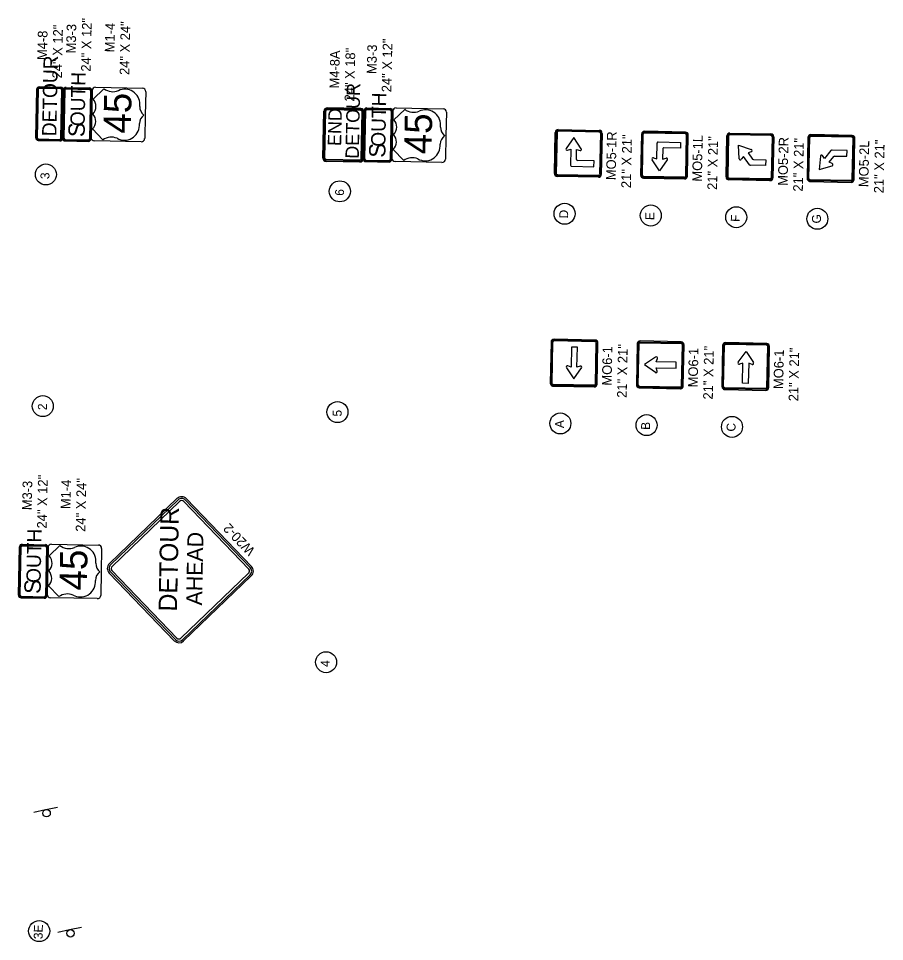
# Model space of a CAD drawing. Extents: x 327762 to 372792, y 127949 to 259367.
# Drawn here: x 351032 to 363148, y 246453 to 259367 of the extents above; entities that cross this region are included whole.
import ezdxf

# ---------------------------------------------------------------- set-up
doc = ezdxf.new("R2010")
doc.units = 0
for name, color, linetype in [('CA-TEXT', 7, 'Continuous'), ('P_SGN_Cell', 7, 'Continuous'), ('SIGNS-POLES', 7, 'Continuous')]:
    doc.layers.add(name, color=color, linetype=linetype)

msp = doc.modelspace()

# ---------------------------------------------------------------- linework, layer by layer
at = {"layer": 'CA-TEXT'}
for centre in [(351416, 257184), (355528, 256948), (358672, 256635), (359878, 256610), (361073, 256586), (362208, 256564), (351373, 253943), (355495, 253860), (358613, 253701), (359819, 253677), (361014, 253653), (355336, 250361), (351322, 246599)]:
    msp.add_circle(centre, 147, dxfattribs=at)
at = {"layer": 'P_SGN_Cell'}
for p, q in [((352110, 258404), (352766, 258390)), ((351648, 257690), (351662, 258366)), ((351658, 257691), (351671, 258366)), ((351670, 257690), (351684, 258365)), ((351700, 258402), (352025, 258396)), ((351700, 258393), (352025, 258387)), ((351700, 258381), (352025, 258374)), ((352040, 258358), (352026, 257683)), ((352052, 258358), (352039, 257683)), ((352062, 258358), (352048, 257683)), ((352048, 257702), (352062, 258358)), ((352229, 258383), (352077, 258238)), ((352812, 258343), (352805, 258014)), ((352812, 258343), (352812, 258343)), ((352730, 258135), (352730, 258165)), ((355292, 257414), (355306, 258070)), ((355304, 257413), (355317, 258069)), ((355320, 257413), (355333, 258069)), ((355822, 258106), (355353, 258116)), ((355822, 258094), (355353, 258104)), ((355821, 258079), (355353, 258088)), ((355827, 257403), (355841, 258059)), ((355843, 257402), (355856, 258059)), ((355855, 257402), (355868, 258078)), ((355855, 257402), (355868, 258058)), ((355864, 257403), (355878, 258077)), ((355877, 257402), (355890, 258077)), ((355906, 258105), (356231, 258098)), ((355906, 258092), (356231, 258086)), ((355907, 258114), (356232, 258108)), ((356246, 258070), (356233, 257395)), ((356259, 258070), (356245, 257395)), ((356255, 257413), (356268, 258069)), ((356268, 258069), (356255, 257395)), ((356435, 258095), (356283, 257949)), ((356316, 258115), (356972, 258102)), ((357018, 258054), (357011, 257726)), ((357018, 258054), (357018, 258054)), ((352724, 257867), (352725, 257897)), ((352805, 258014), (352798, 257686)), ((352068, 257821), (352214, 257669)), ((356936, 257847), (356937, 257877)), ((358530, 257199), (358542, 257773)), ((358553, 257772), (358541, 257198)), ((358567, 257772), (358555, 257198)), ((359157, 257777), (358583, 257788)), ((358584, 257813), (359158, 257801)), ((359158, 257790), (358584, 257802)), ((359173, 257760), (359162, 257186)), ((359187, 257760), (359176, 257186)), ((359198, 257759), (359186, 257185)), ((360363, 257777), (359789, 257789)), ((360363, 257766), (359789, 257778)), ((360363, 257752), (359789, 257764)), ((360984, 257764), (361558, 257753)), ((351685, 257674), (352010, 257668)), ((351685, 257662), (352010, 257655)), ((351685, 257653), (352010, 257646)), ((352751, 257641), (352094, 257654)), ((357011, 257726), (357005, 257398)), ((358803, 257702), (358693, 257549)), ((358906, 257545), (358803, 257702)), ((359747, 257748), (359736, 257174)), ((359747, 257174), (359758, 257748)), ((359760, 257174), (359772, 257748)), ((359983, 257640), (360295, 257633)), ((360295, 257633), (360293, 257551)), ((360367, 257162), (360379, 257736)), ((360381, 257161), (360392, 257735)), ((360392, 257161), (360403, 257735)), ((360931, 257150), (360942, 257724)), ((360953, 257724), (360942, 257150)), ((360967, 257724), (360955, 257150)), ((361558, 257742), (360984, 257754)), ((361558, 257728), (360984, 257740)), ((361574, 257712), (361562, 257138)), ((361588, 257711), (361576, 257137)), ((361599, 257711), (361587, 257137)), ((362077, 257701), (362066, 257127)), ((362077, 257127), (362088, 257701)), ((362090, 257127), (362102, 257701)), ((362693, 257730), (362119, 257742)), ((362693, 257719), (362119, 257731)), ((362693, 257705), (362119, 257717)), ((362697, 257115), (362709, 257689)), ((362711, 257114), (362723, 257688)), ((362722, 257114), (362733, 257688)), ((356275, 257533), (356421, 257381)), ((356931, 257579), (356931, 257609)), ((358711, 257524), (358759, 257537)), ((358759, 257537), (358754, 257314)), ((358838, 257392), (358841, 257535)), ((358841, 257535), (358888, 257520)), ((359962, 257401), (359966, 257624)), ((360047, 257543), (360044, 257399)), ((360293, 257551), (360061, 257556)), ((361114, 257405), (361106, 257592)), ((361106, 257592), (361284, 257532)), ((361284, 257502), (361238, 257485)), ((362398, 257518), (362307, 257407)), ((362623, 257521), (362413, 257525)), ((362622, 257439), (362623, 257521)), ((355807, 257384), (355339, 257393)), ((355807, 257368), (355339, 257377)), ((355892, 257386), (356217, 257380)), ((355892, 257374), (356217, 257367)), ((359084, 257373), (358851, 257378)), ((359082, 257291), (359084, 257373)), ((359999, 257235), (359896, 257391)), ((359915, 257416), (359962, 257401)), ((360109, 257387), (359999, 257235)), ((360044, 257399), (360091, 257413)), ((361173, 257435), (361143, 257396)), ((361259, 257321), (361173, 257435)), ((361238, 257485), (361302, 257400)), ((361313, 257394), (361485, 257391)), ((361485, 257391), (361484, 257309)), ((362250, 257440), (362235, 257253)), ((362307, 257407), (362280, 257448)), ((362371, 257355), (362438, 257437)), ((362449, 257442), (362622, 257439)), ((355807, 257356), (355338, 257366)), ((355891, 257364), (356216, 257358)), ((356957, 257352), (356301, 257366)), ((358770, 257298), (359082, 257291)), ((361484, 257309), (361274, 257313)), ((362235, 257253), (362415, 257305)), ((362417, 257336), (362371, 257355)), ((359145, 257170), (358571, 257181)), ((359145, 257156), (358571, 257168)), ((359145, 257145), (358571, 257157)), ((360350, 257146), (359776, 257157)), ((360350, 257132), (359776, 257143)), ((359776, 257132), (360350, 257121)), ((361545, 257108), (360971, 257119)), ((361546, 257121), (360972, 257133)), ((361545, 257097), (360971, 257108)), ((362681, 257099), (362106, 257110)), ((362680, 257085), (362106, 257096)), ((362106, 257086), (362680, 257074)), ((358483, 254839), (358471, 254265)), ((358482, 254265), (358494, 254839)), ((358496, 254265), (358507, 254839)), ((359099, 254857), (358524, 254868)), ((359098, 254843), (358524, 254855)), ((359099, 254868), (358525, 254879)), ((359103, 254252), (359114, 254826)), ((359116, 254252), (359128, 254826)), ((359127, 254252), (359139, 254826)), ((359688, 254815), (359677, 254241)), ((359687, 254241), (359699, 254815)), ((359701, 254240), (359713, 254814)), ((359729, 254830), (360304, 254819)), ((360304, 254843), (359730, 254855)), ((359730, 254844), (360304, 254833)), ((360308, 254228), (360320, 254802)), ((360322, 254228), (360333, 254802)), ((360333, 254228), (360344, 254802)), ((360883, 254791), (360872, 254217)), ((360883, 254216), (360894, 254791)), ((360896, 254216), (360908, 254790)), ((361499, 254819), (360925, 254831)), ((361499, 254808), (360925, 254820)), ((361499, 254795), (360925, 254806)), ((358769, 254770), (358763, 254490)), ((358851, 254769), (358769, 254770)), ((358845, 254489), (358851, 254769)), ((361100, 254556), (361210, 254708)), ((361210, 254708), (361313, 254552)), ((361503, 254204), (361515, 254778)), ((361517, 254204), (361528, 254778)), ((361528, 254203), (361539, 254778)), ((359946, 254629), (359789, 254526)), ((359955, 254563), (359970, 254610)), ((360235, 254558), (359955, 254563)), ((360234, 254476), (360235, 254558)), ((361166, 254544), (361118, 254530)), ((361160, 254264), (361166, 254544)), ((361248, 254542), (361242, 254262)), ((361294, 254527), (361248, 254542)), ((358697, 254481), (358801, 254324)), ((358763, 254490), (358716, 254506)), ((358801, 254324), (358910, 254477)), ((358892, 254502), (358845, 254489)), ((359789, 254526), (359942, 254416)), ((359967, 254434), (359954, 254481)), ((359954, 254481), (360234, 254476)), ((358511, 254223), (359086, 254212)), ((359086, 254236), (358512, 254248)), ((359086, 254223), (358512, 254234)), ((359717, 254224), (360291, 254212)), ((359717, 254210), (360291, 254198)), ((359717, 254199), (360291, 254187)), ((361487, 254188), (360912, 254199)), ((361486, 254174), (360912, 254186)), ((360912, 254175), (361486, 254163)), ((361242, 254262), (361160, 254264)), ((351032, 251299), (351046, 251975)), ((351042, 251300), (351055, 251975)), ((351054, 251300), (351068, 251974)), ((351084, 252012), (351409, 252005)), ((351084, 252002), (351409, 251996)), ((351084, 251990), (351409, 251983)), ((351424, 251967), (351411, 251292)), ((351437, 251967), (351423, 251292)), ((351446, 251967), (351432, 251292)), ((351433, 251311), (351446, 251967)), ((351613, 251992), (351461, 251847)), ((351494, 252013), (352150, 251999)), ((352196, 251952), (352189, 251624)), ((352196, 251952), (352196, 251952)), ((352114, 251744), (352115, 251774)), ((352189, 251624), (352183, 251296)), ((351453, 251430), (351598, 251278)), ((352109, 251476), (352109, 251506)), ((351069, 251271), (351394, 251265)), ((351069, 251262), (351394, 251255)), ((351070, 251284), (351395, 251277)), ((352135, 251250), (351479, 251263))]:
    msp.add_line(p, q, dxfattribs=at)
for points in [[(351625, 258403), (351325, 258409)], [(351287, 258373), (351273, 257698)], [(351296, 258373), (351283, 257698)], [(351309, 258372), (351295, 257697)], [(351625, 258394), (351325, 258400)], [(351625, 258382), (351325, 258388)], [(351626, 257691), (351640, 258366)], [(351639, 257691), (351652, 258365)], [(351648, 257690), (351662, 258365)], [(351310, 257682), (351610, 257675)], [(351310, 257669), (351610, 257663)], [(351310, 257660), (351610, 257654)], [(353250, 252649), (352304, 251740)], [(353267, 252632), (352320, 251723)], [(353287, 252610), (352341, 251701)], [(354253, 251664), (353344, 252610)], [(354274, 251684), (353365, 252630)], [(354291, 251701), (353383, 252647)], [(352301, 251607), (353210, 250661)], [(352318, 251624), (353228, 250677)], [(352340, 251644), (353249, 250698)], [(353306, 250697), (354252, 251606)], [(353326, 250675), (354273, 251585)], [(353343, 250658), (354289, 251567)]]:
    msp.add_lwpolyline(points, dxfattribs=at)
for centre, radius, start, end in [((351324, 258372), 37.5, 88.8468, 178.8468), ((351624, 258366), 37.5, 358.8468, 88.8468), ((352109, 258357), 46.9, 88.8462, 178.8462), ((351324, 258372), 28.1, 88.8468, 178.8468), ((351324, 258372), 15.6, 88.8468, 178.8468), ((351624, 258366), 28.1, 358.8468, 88.8468), ((351624, 258366), 15.6, 358.8468, 88.8468), ((351699, 258365), 37.5, 88.8462, 178.8462), ((351699, 258365), 28.1, 88.8462, 178.8462), ((351699, 258365), 15.6, 88.8462, 178.8462), ((352024, 258358), 37.5, 358.8462, 88.8462), ((352024, 258358), 28.1, 358.8462, 88.8462), ((352024, 258358), 15.6, 358.8462, 88.8462), ((352354, 258550), 208, 233.1143, 291.9873), ((352522, 258169), 208, 358.8462, 115.6928), ((352765, 258343), 46.9, 358.8462, 88.8462), ((351968, 258136), 149, 314.4191, 43.2734), ((351964, 257927), 149, 314.4191, 43.2734), ((352880, 258133), 151, 179.1885, 231.634), ((355352, 258069), 46.9, 88.8468, 178.8468), ((355352, 258069), 35.2, 88.8468, 178.8468), ((355352, 258069), 19.5, 88.8468, 178.8468), ((355821, 258059), 19.5, 358.8468, 88.8468), ((355821, 258059), 46.9, 358.8468, 88.8468), ((355821, 258059), 35.2, 358.8468, 88.8468), ((355906, 258077), 37.5, 88.8462, 178.8462), ((355906, 258077), 28.1, 88.8462, 178.8462), ((355906, 258077), 15.6, 88.8462, 178.8462), ((356231, 258070), 28.1, 358.8462, 88.8462), ((356231, 258070), 15.6, 358.8462, 88.8462), ((356231, 258070), 37.5, 358.8462, 88.8462), ((356315, 258069), 46.9, 88.8462, 178.8462), ((356560, 258262), 208, 233.1143, 291.9873), ((356728, 257881), 208, 358.8462, 115.6928), ((356971, 258055), 46.9, 358.8462, 88.8462), ((352875, 257893), 151, 126.0584, 178.5039), ((356175, 257847), 149, 314.4191, 43.2734), ((352516, 257871), 208, 240.0981, 358.8463), ((357087, 257845), 151, 179.1885, 231.634), ((358583, 257772), 41, 88.8462, 178.8462), ((358583, 257772), 30.1, 88.8462, 178.8462), ((358583, 257772), 16.4, 88.8462, 178.8462), ((359157, 257760), 16.4, 358.8462, 88.8462), ((359157, 257760), 41, 358.8462, 88.8462), ((359157, 257760), 30.1, 358.8462, 88.8462), ((359788, 257748), 41, 88.8462, 178.8462), ((359788, 257748), 30.1, 88.8462, 178.8462), ((359788, 257748), 16.4, 88.8462, 178.8462), ((360362, 257736), 41, 358.8462, 88.8462), ((360362, 257736), 30.1, 358.8462, 88.8462), ((360983, 257723), 41, 88.8462, 178.8462), ((360983, 257723), 41, 88.8462, 113.5578), ((351311, 257697), 37.5, 178.8468, 268.8468), ((351311, 257697), 28.1, 178.8468, 268.8468), ((351311, 257697), 15.6, 178.8468, 268.8468), ((351311, 257697), 15.6, 178.8468, 186.1883), ((351611, 257691), 28.1, 268.8468, 358.8468), ((351611, 257691), 15.6, 268.8468, 358.8468), ((351611, 257691), 37.5, 268.8468, 358.8468), ((351686, 257690), 37.5, 179.6119, 268.8462), ((351686, 257690), 28.1, 178.8462, 268.8462), ((351686, 257690), 15.6, 178.8462, 268.8462), ((352011, 257684), 28.1, 268.8462, 358.8462), ((352011, 257684), 15.6, 268.8462, 358.8462), ((352011, 257684), 37.5, 268.8462, 358.8462), ((352095, 257701), 46.9, 178.8462, 268.8462), ((352333, 257498), 208, 67.7159, 124.7982), ((352751, 257687), 46.9, 268.8462, 358.8462), ((356171, 257639), 149, 314.4191, 43.2734), ((357082, 257605), 151, 126.0584, 178.5039), ((359983, 257623), 16.4, 88.8462, 178.8462), ((360362, 257736), 16.4, 358.8462, 88.8462), ((360983, 257723), 41, 144.5056, 178.8462), ((360983, 257723), 30.1, 88.8462, 178.8462), ((360983, 257723), 16.4, 88.8462, 178.8462), ((361558, 257712), 41, 358.8462, 88.8462), ((361558, 257712), 30.1, 358.8462, 88.8462), ((361558, 257712), 16.4, 358.8462, 88.8462), ((362118, 257701), 41, 88.8462, 178.8462), ((362118, 257701), 30.1, 88.8462, 178.8462), ((362118, 257701), 16.4, 88.8462, 178.8462), ((362692, 257689), 41, 358.8462, 88.8462), ((362692, 257689), 30.1, 358.8462, 88.8462), ((362692, 257689), 16.4, 358.8462, 88.8462), ((356722, 257583), 208, 240.0981, 358.8463), ((358707, 257540), 16.4, 144.3166, 285.6488), ((358893, 257536), 16.4, 252.0436, 33.3759), ((360060, 257542), 13.7, 88.8462, 178.8462), ((361279, 257517), 16.4, 290.0436, 71.3759), ((362413, 257506), 19.1, 88.8462, 140.8466), ((355339, 257413), 46.9, 178.8468, 268.8468), ((355339, 257413), 35.2, 178.8468, 268.8468), ((355339, 257413), 19.5, 178.8468, 268.8468), ((355339, 257413), 19.5, 178.8468, 187.6911), ((355808, 257403), 19.5, 268.8468, 358.8468), ((355808, 257403), 46.9, 268.8468, 358.8468), ((355808, 257403), 35.2, 268.8468, 358.8468), ((355892, 257402), 37.5, 179.6119, 268.8462), ((355892, 257402), 28.1, 178.8462, 268.8462), ((355892, 257402), 15.6, 178.8462, 268.8462), ((356217, 257395), 37.5, 268.8462, 358.8462), ((356217, 257395), 28.1, 268.8462, 358.8462), ((356217, 257395), 15.6, 268.8462, 358.8462), ((356302, 257412), 46.9, 178.8462, 268.8462), ((356540, 257210), 208, 67.7159, 124.7982), ((356958, 257399), 46.9, 268.8462, 358.8462), ((358852, 257392), 13.7, 178.8462, 268.8462), ((359910, 257401), 16.4, 72.0436, 213.3759), ((360096, 257397), 16.4, 324.3166, 105.6488), ((361130, 257405), 16.4, 182.3166, 323.6488), ((361313, 257408), 13.7, 216.8461, 268.8462), ((362266, 257438), 16.4, 34.0436, 175.3759), ((362449, 257429), 13.7, 88.8462, 140.8463), ((358771, 257314), 16.4, 178.8462, 268.8462), ((361274, 257332), 19.1, 216.8459, 268.8462), ((362410, 257321), 16.4, 286.3166, 67.6488), ((358571, 257198), 41, 178.8462, 268.8462), ((358571, 257198), 30.1, 178.8462, 268.8462), ((358571, 257198), 16.4, 178.8462, 268.8462), ((359145, 257186), 16.4, 268.8462, 358.8462), ((359145, 257186), 30.1, 268.8462, 358.8462), ((359145, 257186), 41, 268.8462, 358.8462), ((359777, 257173), 41, 178.8462, 268.8462), ((359777, 257173), 30.1, 178.8462, 268.8462), ((359777, 257173), 16.4, 178.8462, 268.8462), ((360351, 257162), 16.4, 268.8462, 358.8462), ((360351, 257162), 30.1, 268.8462, 358.8462), ((360351, 257162), 41, 268.8462, 358.8462), ((360972, 257149), 41, 178.8462, 268.8462), ((360972, 257149), 30.1, 178.8462, 268.8462), ((360972, 257149), 16.4, 178.8462, 268.8462), ((361546, 257138), 30.1, 268.8462, 358.8462), ((361546, 257138), 41, 268.8462, 358.8462), ((361546, 257138), 16.4, 268.8462, 358.8462), ((362107, 257127), 41, 178.8462, 268.8462), ((362107, 257127), 41, 178.8462, 213.1868), ((362107, 257127), 30.1, 178.8462, 268.8462), ((362107, 257127), 16.4, 178.8462, 268.8462), ((362681, 257115), 30.1, 268.8462, 358.8462), ((362681, 257115), 41, 268.8462, 358.8462), ((362681, 257115), 16.4, 268.8462, 358.8462), ((362107, 257127), 41, 244.1347, 268.8462), ((358524, 254838), 41, 88.8462, 178.8462), ((358524, 254838), 30.1, 88.8462, 178.8462), ((358524, 254838), 16.4, 88.8462, 178.8462), ((359098, 254827), 16.4, 358.8462, 88.8462), ((359098, 254827), 41, 358.8462, 88.8462), ((359098, 254827), 30.1, 358.8462, 88.8462), ((359729, 254814), 41, 88.8462, 178.8462), ((359729, 254814), 41, 149.4497, 178.8462), ((359729, 254814), 30.1, 88.8462, 178.8462), ((359729, 254814), 16.4, 88.8462, 178.8462), ((360303, 254802), 41, 358.8462, 88.8462), ((360303, 254802), 30.1, 358.8462, 88.8462), ((360303, 254802), 16.4, 358.8462, 88.8462), ((360924, 254790), 41, 88.8462, 178.8462), ((360924, 254790), 30.1, 88.8462, 178.8462), ((360924, 254790), 16.4, 88.8462, 178.8462), ((361498, 254778), 41, 358.8462, 88.8462), ((361498, 254778), 30.1, 358.8462, 88.8462), ((361498, 254778), 16.4, 358.8462, 88.8462), ((359955, 254615), 16.4, 342.0436, 123.3759), ((361114, 254546), 16.4, 144.3166, 285.6488), ((361300, 254542), 16.4, 252.0436, 33.3759), ((358711, 254490), 16.4, 72.0436, 213.3759), ((358897, 254486), 16.4, 324.3166, 105.6488), ((359951, 254429), 16.4, 234.3166, 15.6488), ((358512, 254264), 41, 178.8462, 268.8462), ((358512, 254264), 30.1, 178.8462, 268.8462), ((358512, 254264), 41, 239.4497, 268.8462), ((358512, 254264), 16.4, 178.8462, 268.8462), ((359086, 254253), 30.1, 268.8462, 358.8462), ((359086, 254253), 41, 268.8462, 358.8462), ((359086, 254253), 16.4, 268.8462, 358.8462), ((359718, 254240), 41, 178.8462, 268.8462), ((359718, 254240), 30.1, 178.8462, 268.8462), ((359718, 254240), 16.4, 178.8462, 268.8462), ((360292, 254228), 30.1, 268.8462, 358.8462), ((360292, 254228), 41, 268.8462, 358.8462), ((360292, 254228), 16.4, 268.8462, 358.8462), ((360913, 254216), 41, 178.8462, 268.8462), ((360913, 254216), 30.1, 178.8462, 268.8462), ((360913, 254216), 41, 239.4497, 268.8462), ((360913, 254216), 16.4, 178.8462, 268.8462), ((361487, 254204), 30.1, 268.8462, 358.8462), ((361487, 254204), 41, 268.8462, 358.8462), ((361487, 254204), 16.4, 268.8462, 358.8462), ((353315, 252582), 93.7, 43.8468, 133.8468), ((353315, 252582), 69.9, 43.8468, 133.8468), ((353315, 252582), 40.2, 43.8468, 133.8468), ((351084, 251974), 37.5, 88.8462, 178.8462), ((351084, 251974), 28.1, 88.8462, 178.8462), ((351084, 251974), 15.6, 88.8462, 178.8462), ((351408, 251968), 37.5, 358.8462, 88.8462), ((351408, 251968), 28.1, 358.8462, 88.8462), ((351408, 251968), 15.6, 358.8462, 88.8462), ((351493, 251966), 46.9, 88.8462, 178.8462), ((351738, 252159), 208, 233.1143, 291.9873), ((351906, 251778), 208, 358.8462, 115.6928), ((352149, 251953), 46.9, 358.8462, 88.8462), ((351353, 251745), 149, 314.4191, 43.2734), ((352265, 251742), 151, 179.1885, 231.634), ((352369, 251672), 93.7, 133.8449, 223.8468), ((352369, 251672), 69.9, 133.8449, 223.8468), ((352369, 251672), 40.2, 133.8449, 223.8468), ((354225, 251635), 93.7, 313.854, 44.4977), ((351348, 251536), 149, 314.4191, 43.2734), ((352260, 251502), 151, 126.0584, 178.5039), ((354225, 251635), 40.2, 313.854, 44.4977), ((354225, 251635), 69.9, 313.854, 44.4977), ((351900, 251481), 208, 240.0981, 358.8463), ((351480, 251310), 46.9, 178.8462, 268.8462), ((351717, 251107), 208, 67.7159, 124.7982), ((351070, 251299), 37.5, 179.6119, 268.8462), ((351070, 251299), 28.1, 178.8462, 268.8462), ((351070, 251299), 15.6, 178.8462, 268.8462), ((351395, 251293), 28.1, 268.8462, 358.8462), ((351395, 251293), 37.5, 268.8462, 358.8462), ((351395, 251293), 15.6, 268.8462, 358.8462), ((352136, 251297), 46.9, 268.8462, 358.8462), ((353278, 250726), 93.7, 223.8468, 313.8468), ((353278, 250726), 69.9, 223.8468, 313.8468), ((353278, 250726), 40.2, 223.8468, 313.8468)]:
    msp.add_arc(centre, radius, start, end, dxfattribs=at)
at = {"layer": 'SIGNS-POLES'}
for p, q in [((351414, 248298), (351579, 248331)), ((351247, 248265), (351412, 248299)), ((351581, 246586), (351746, 246620)), ((351748, 246619), (351913, 246652))]:
    msp.add_line(p, q, dxfattribs=at)
for centre in [(351426, 248248), (351760, 246568)]:
    msp.add_circle(centre, 52.2, dxfattribs=at)

# ---------------------------------------------------------------- texts
at = {"layer": 'CA-TEXT'}
for s, p in [('3', (351465, 257118)), ('6', (355586, 256885)), ('D', (358721, 256568)), ('E', (359926, 256544)), ('F', (361122, 256520)), ('G', (362257, 256497)), ('2', (351429, 253886)), ('5', (355553, 253797)), ('A', (358662, 253635)), ('B', (359867, 253610)), ('C', (361062, 253586)), ('4', (355385, 250294)), ('3E', (351370, 246485))]:
    msp.add_text(s, height=125, rotation=88.8468, dxfattribs=at).set_placement(p)
at = {"layer": 'P_SGN_Cell'}
for s, height, rotation, p in [('24" X 12"', 135, 88.8462, (352043, 258621)), ('24" X 24"', 135, 88.8462, (352582, 258575)), ('M4-8', 135, 88.8468, (351431, 258784)), ('24" X 12"', 135, 88.8468, (351640, 258528)), ('M3-3', 135, 88.8462, (351834, 258877)), ('M1-4', 135, 88.8462, (352375, 258892)), ('24" X 12"', 135, 88.8462, (356249, 258333)), ('24" X 18"', 135, 88.8468, (355729, 258204)), ('M3-3', 135, 88.8462, (356040, 258589)), ('DETOUR', 200, 88.8468, (351562, 257717)), ('M4-8A', 135, 88.8468, (355518, 258386)), ('OUTH', 200, 88.8462, (351958, 257858)), ('DETOUR', 187.5, 88.8468, (355793, 257403)), ('45', 383.3, 88.8462, (352603, 257753)), ('OUTH', 200, 88.8462, (356164, 257570)), ('END', 187.5, 88.8468, (355546, 257581)), ('45', 383.3, 88.8462, (356810, 257465)), ('S', 229, 88.8462, (351958, 257705)), ('MO5-1R', 135, 88.8462, (359387, 257103)), ('21" X 21"', 135, 88.8462, (359599, 256992)), ('MO5-1L', 135, 88.8462, (360592, 257083)), ('21" X 21"', 135, 88.8462, (360804, 256967)), ('MO5-2R', 135, 88.8462, (361791, 257024)), ('21" X 21"', 135, 88.8462, (362004, 256943)), ('MO5-2L', 135, 88.8462, (362921, 257005)), ('21" X 21"', 135, 88.8462, (363134, 256920)), ('S', 229, 88.8462, (356164, 257417)), ('21" X 21"', 135, 88.8462, (359540, 254058)), ('MO6-1', 135, 88.8462, (359329, 254229)), ('MO6-1', 135, 88.8462, (360534, 254205)), ('21" X 21"', 135, 88.8462, (360745, 254034)), ('MO6-1', 135, 88.8462, (361729, 254181)), ('21" X 21"', 135, 88.8462, (361940, 254010)), ('M3-3', 135, 88.8462, (351218, 252486)), ('24" X 12"', 135, 88.8462, (351427, 252230)), ('M1-4', 135, 88.8462, (351759, 252501)), ('24" X 24"', 135, 88.8462, (351967, 252184)), ('DETOUR', 258.9, 88.8468, (353250, 251068)), ('OUTH', 200, 88.8462, (351342, 251468)), ('W20-2', 135, 133.8468, (354351, 251930)), ('AHEAD', 223.2, 88.8468, (353600, 251153)), ('45', 383.3, 88.8462, (351988, 251362)), ('S', 229, 88.8462, (351342, 251314))]:
    msp.add_text(s, height=height, rotation=rotation, dxfattribs=at).set_placement(p)

doc.saveas('drawing.dxf')
